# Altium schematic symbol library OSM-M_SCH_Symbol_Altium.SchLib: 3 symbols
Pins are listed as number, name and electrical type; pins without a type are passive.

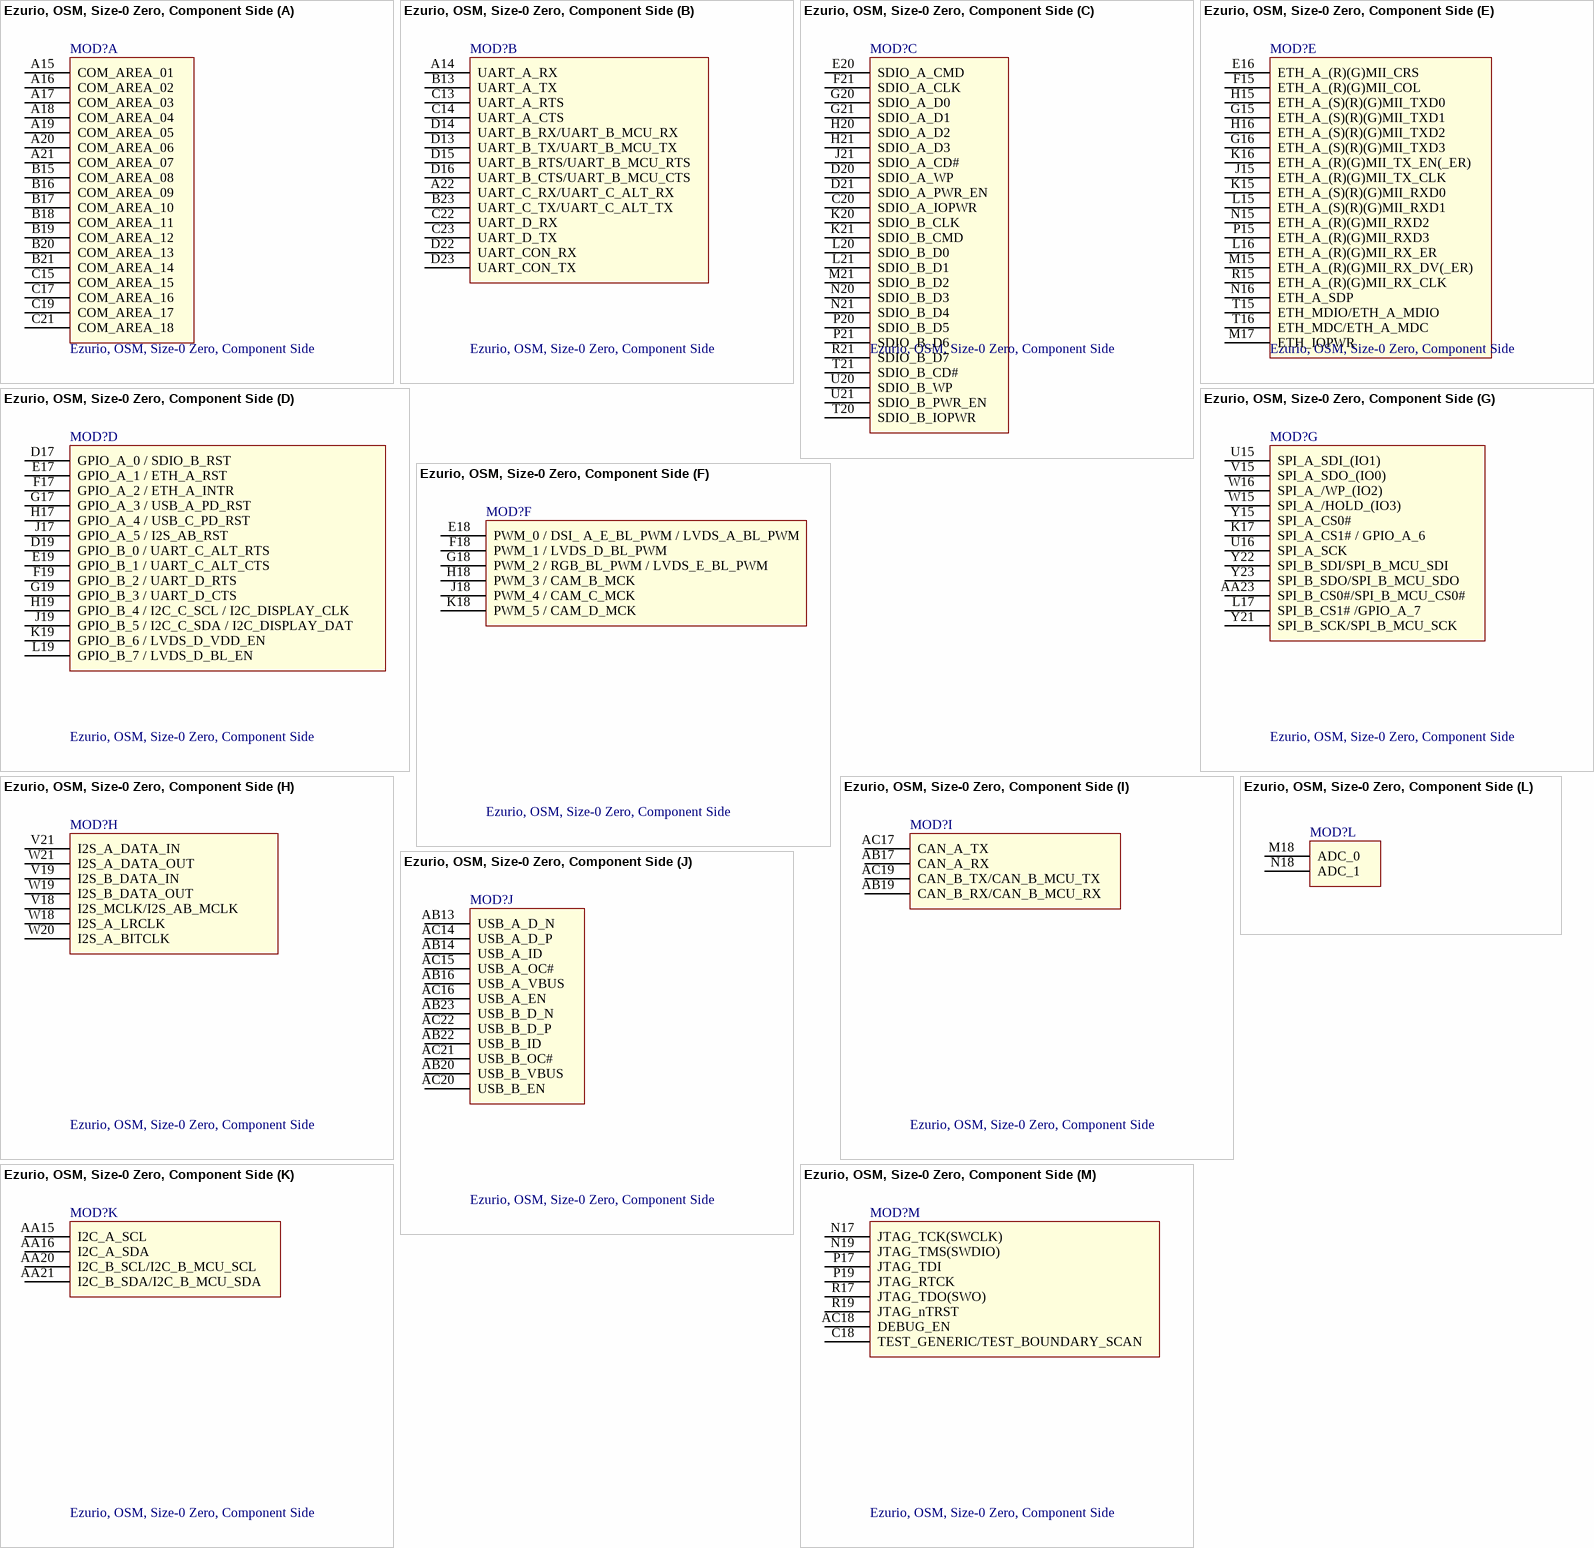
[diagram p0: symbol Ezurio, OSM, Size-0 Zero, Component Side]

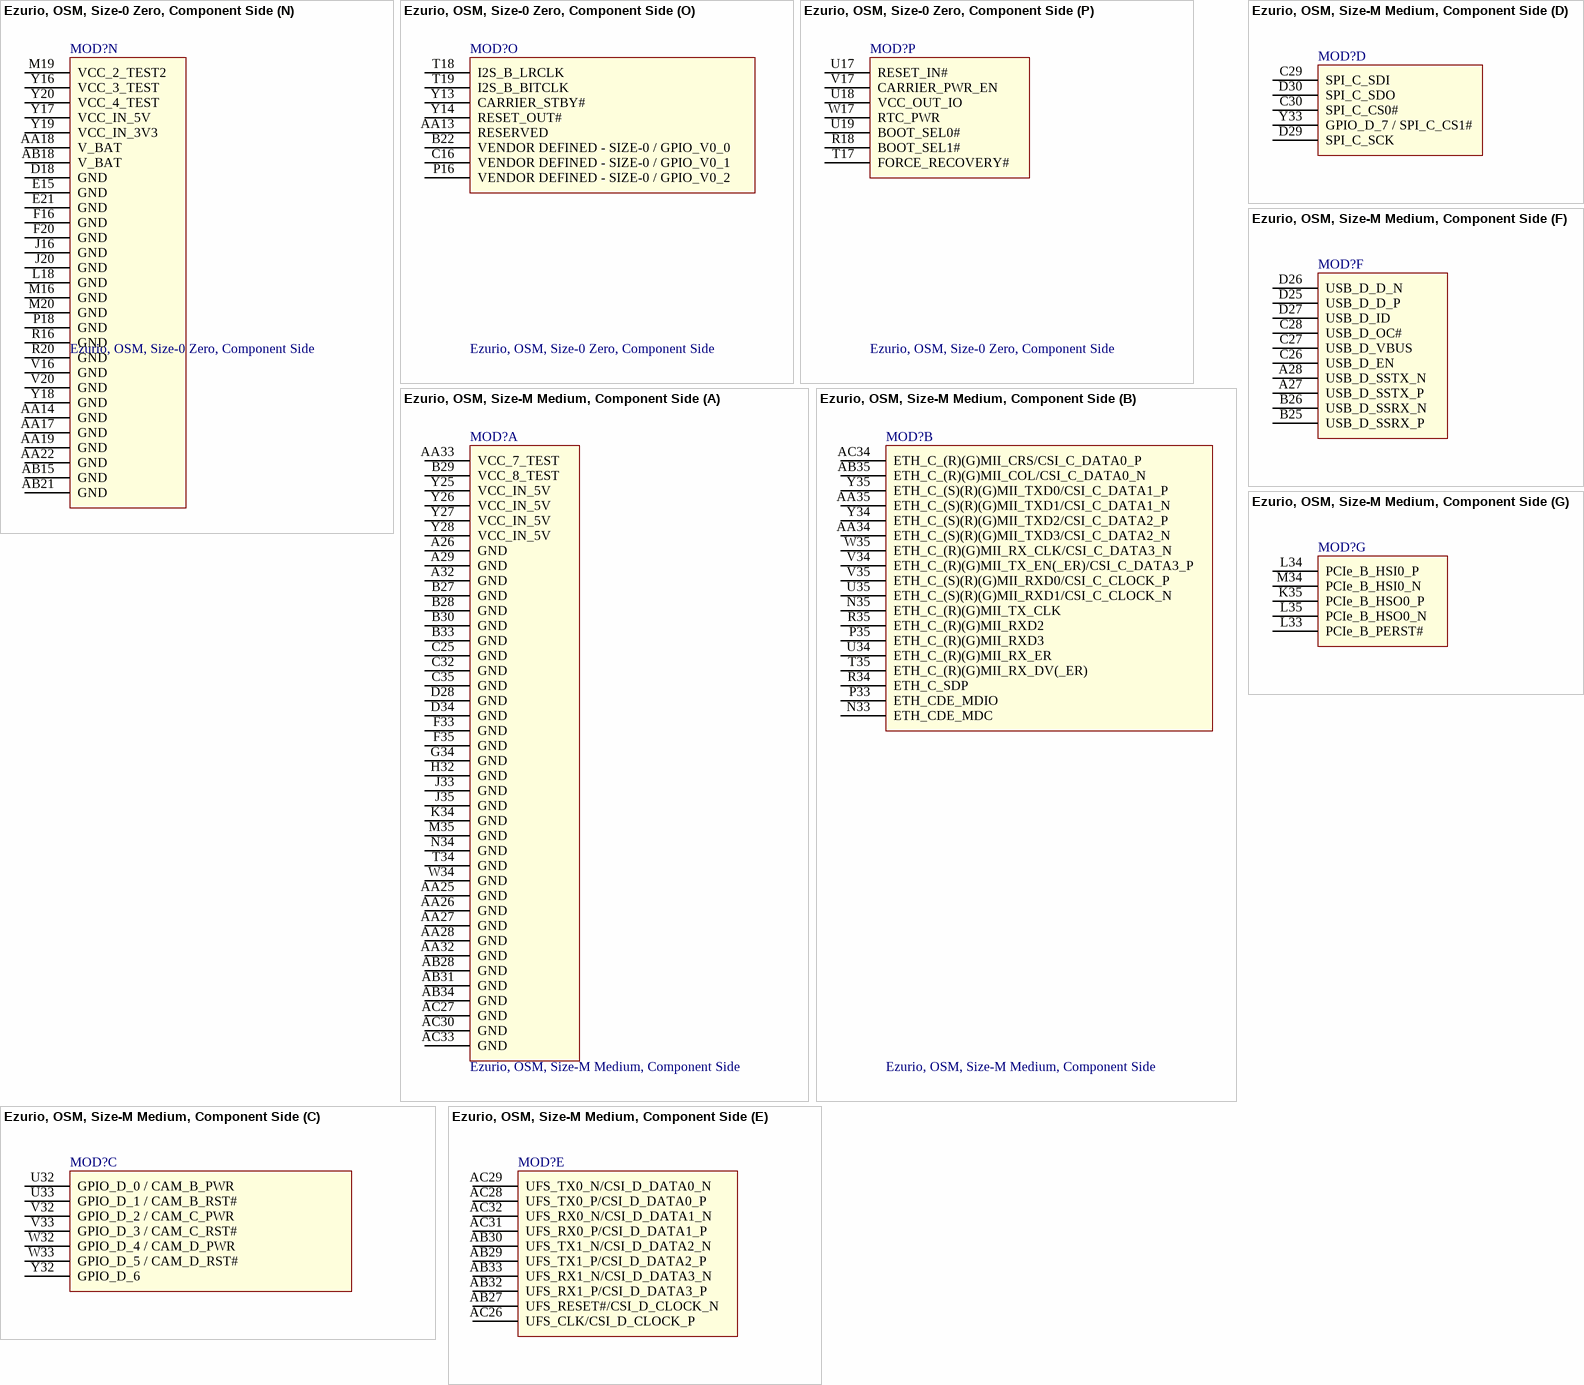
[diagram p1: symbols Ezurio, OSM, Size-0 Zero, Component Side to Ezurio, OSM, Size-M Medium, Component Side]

## Ezurio, OSM, Size-0 Zero, Component Side
designator MOD?
OSM, Size-0 Zero, 30mm X 15mm with 188 contacts; Substitutes Allowed: NO
footprint OSM, Size-0 Zero
part A pins: A15 COM_AREA_01, A16 COM_AREA_02, A17 COM_AREA_03, A18 COM_AREA_04, A19 COM_AREA_05, A20 COM_AREA_06, A21 COM_AREA_07, B15 COM_AREA_08, B16 COM_AREA_09, B17 COM_AREA_10, B18 COM_AREA_11, B19 COM_AREA_12, B20 COM_AREA_13, B21 COM_AREA_14, C15 COM_AREA_15, C17 COM_AREA_16, C19 COM_AREA_17, C21 COM_AREA_18
part B pins: A14 UART_A_RX, A22 UART_C_RX/UART_C_ALT_RX, B13 UART_A_TX, B23 UART_C_TX/UART_C_ALT_TX, C13 UART_A_RTS, C14 UART_A_CTS, C22 UART_D_RX, C23 UART_D_TX, D13 UART_B_TX/UART_B_MCU_TX, D14 UART_B_RX/UART_B_MCU_RX, D15 UART_B_RTS/UART_B_MCU_RTS, D16 UART_B_CTS/UART_B_MCU_CTS, D22 UART_CON_RX, D23 UART_CON_TX
part C pins: C20 SDIO_A_IOPWR, D20 SDIO_A_WP, D21 SDIO_A_PWR_EN, E20 SDIO_A_CMD, F21 SDIO_A_CLK, G20 SDIO_A_D0, G21 SDIO_A_D1, H20 SDIO_A_D2, H21 SDIO_A_D3, J21 SDIO_A_CD#, K20 SDIO_B_CLK, K21 SDIO_B_CMD, L20 SDIO_B_D0, L21 SDIO_B_D1, M21 SDIO_B_D2, N20 SDIO_B_D3, N21 SDIO_B_D4, P20 SDIO_B_D5, P21 SDIO_B_D6, R21 SDIO_B_D7, T20 SDIO_B_IOPWR, T21 SDIO_B_CD#, U20 SDIO_B_WP, U21 SDIO_B_PWR_EN
part D pins: D17 GPIO_A_0 / SDIO_B_RST, D19 GPIO_B_0 / UART_C_ALT_RTS, E17 GPIO_A_1 / ETH_A_RST , E19 GPIO_B_1 / UART_C_ALT_CTS, F17 GPIO_A_2 / ETH_A_INTR, F19 GPIO_B_2 / UART_D_RTS, G17 GPIO_A_3 / USB_A_PD_RST , G19 GPIO_B_3 / UART_D_CTS , H17 GPIO_A_4 / USB_C_PD_RST, H19 GPIO_B_4 / I2C_C_SCL / I2C_DISPLAY_CLK, J17 GPIO_A_5 / I2S_AB_RST, J19 GPIO_B_5 / I2C_C_SDA / I2C_DISPLAY_DAT, K19 GPIO_B_6 / LVDS_D_VDD_EN, L19 GPIO_B_7 / LVDS_D_BL_EN
part E pins: E16 ETH_A_(R)(G)MII_CRS, F15 ETH_A_(R)(G)MII_COL, G15 ETH_A_(S)(R)(G)MII_TXD1, G16 ETH_A_(S)(R)(G)MII_TXD3, H15 ETH_A_(S)(R)(G)MII_TXD0, H16 ETH_A_(S)(R)(G)MII_TXD2, J15 ETH_A_(R)(G)MII_TX_CLK, K15 ETH_A_(S)(R)(G)MII_RXD0, K16 ETH_A_(R)(G)MII_TX_EN(_ER), L15 ETH_A_(S)(R)(G)MII_RXD1, L16 ETH_A_(R)(G)MII_RX_ER, M15 ETH_A_(R)(G)MII_RX_DV(_ER), M17 ETH_IOPWR, N15 ETH_A_(R)(G)MII_RXD2, N16 ETH_A_SDP, P15 ETH_A_(R)(G)MII_RXD3, R15 ETH_A_(R)(G)MII_RX_CLK, T15 ETH_MDIO/ETH_A_MDIO, T16 ETH_MDC/ETH_A_MDC
part F pins: E18 PWM_0 / DSI_ A_E_BL_PWM / LVDS_A_BL_PWM, F18 PWM_1 / LVDS_D_BL_PWM, G18 PWM_2 / RGB_BL_PWM / LVDS_E_BL_PWM, H18 PWM_3 / CAM_B_MCK, J18 PWM_4 / CAM_C_MCK, K18 PWM_5 / CAM_D_MCK
part G pins: AA23 SPI_B_CS0#/SPI_B_MCU_CS0#, K17 SPI_A_CS1# / GPIO_A_6, L17 SPI_B_CS1# /GPIO_A_7, U15 SPI_A_SDI_(IO1), U16 SPI_A_SCK, V15 SPI_A_SDO_(IO0), W15 SPI_A_/HOLD_(IO3), W16 SPI_A_/WP_(IO2), Y15 SPI_A_CS0#, Y21 SPI_B_SCK/SPI_B_MCU_SCK, Y22 SPI_B_SDI/SPI_B_MCU_SDI, Y23 SPI_B_SDO/SPI_B_MCU_SDO
part H pins: V18 I2S_MCLK/I2S_AB_MCLK, V19 I2S_B_DATA_IN, V21 I2S_A_DATA_IN, W18 I2S_A_LRCLK, W19 I2S_B_DATA_OUT, W20 I2S_A_BITCLK, W21 I2S_A_DATA_OUT
part I pins: AB17 CAN_A_RX, AB19 CAN_B_RX/CAN_B_MCU_RX, AC17 CAN_A_TX, AC19 CAN_B_TX/CAN_B_MCU_TX
part J pins: AB13 USB_A_D_N, AB14 USB_A_ID, AB16 USB_A_VBUS, AB20 USB_B_VBUS, AB22 USB_B_ID, AB23 USB_B_D_N, AC14 USB_A_D_P, AC15 USB_A_OC#, AC16 USB_A_EN, AC20 USB_B_EN, AC21 USB_B_OC#, AC22 USB_B_D_P
part K pins: AA15 I2C_A_SCL, AA16 I2C_A_SDA, AA20 I2C_B_SCL/I2C_B_MCU_SCL, AA21 I2C_B_SDA/I2C_B_MCU_SDA
part L pins: M18 ADC_0, N18 ADC_1
part M pins: AC18 DEBUG_EN, C18 TEST_GENERIC/TEST_BOUNDARY_SCAN , N17 JTAG_TCK(SWCLK), N19 JTAG_TMS(SWDIO), P17 JTAG_TDI, P19 JTAG_RTCK, R17 JTAG_TDO(SWO), R19 JTAG_nTRST
part N pins: AA14 GND, AA17 GND, AA18 V_BAT, AA19 GND, AA22 GND, AB15 GND, AB18 V_BAT, AB21 GND, D18 GND, E15 GND, E21 GND, F16 GND, F20 GND, J16 GND, J20 GND, L18 GND, M16 GND, M19 VCC_2_TEST2, M20 GND, P18 GND, R16 GND, R20 GND, V16 GND, V20 GND, Y16 VCC_3_TEST, Y17 VCC_IN_5V, Y18 GND, Y19 VCC_IN_3V3, Y20 VCC_4_TEST
part O pins: AA13 RESERVED, B22 VENDOR DEFINED - SIZE-0 / GPIO_V0_0, C16 VENDOR DEFINED - SIZE-0 / GPIO_V0_1, P16 VENDOR DEFINED - SIZE-0 / GPIO_V0_2, T18 I2S_B_LRCLK, T19 I2S_B_BITCLK, Y13 CARRIER_STBY#, Y14 RESET_OUT#
part P pins: R18 BOOT_SEL1#, T17 FORCE_RECOVERY#, U17 RESET_IN#, U18 VCC_OUT_IO, U19 BOOT_SEL0#, V17 CARRIER_PWR_EN, W17 RTC_PWR

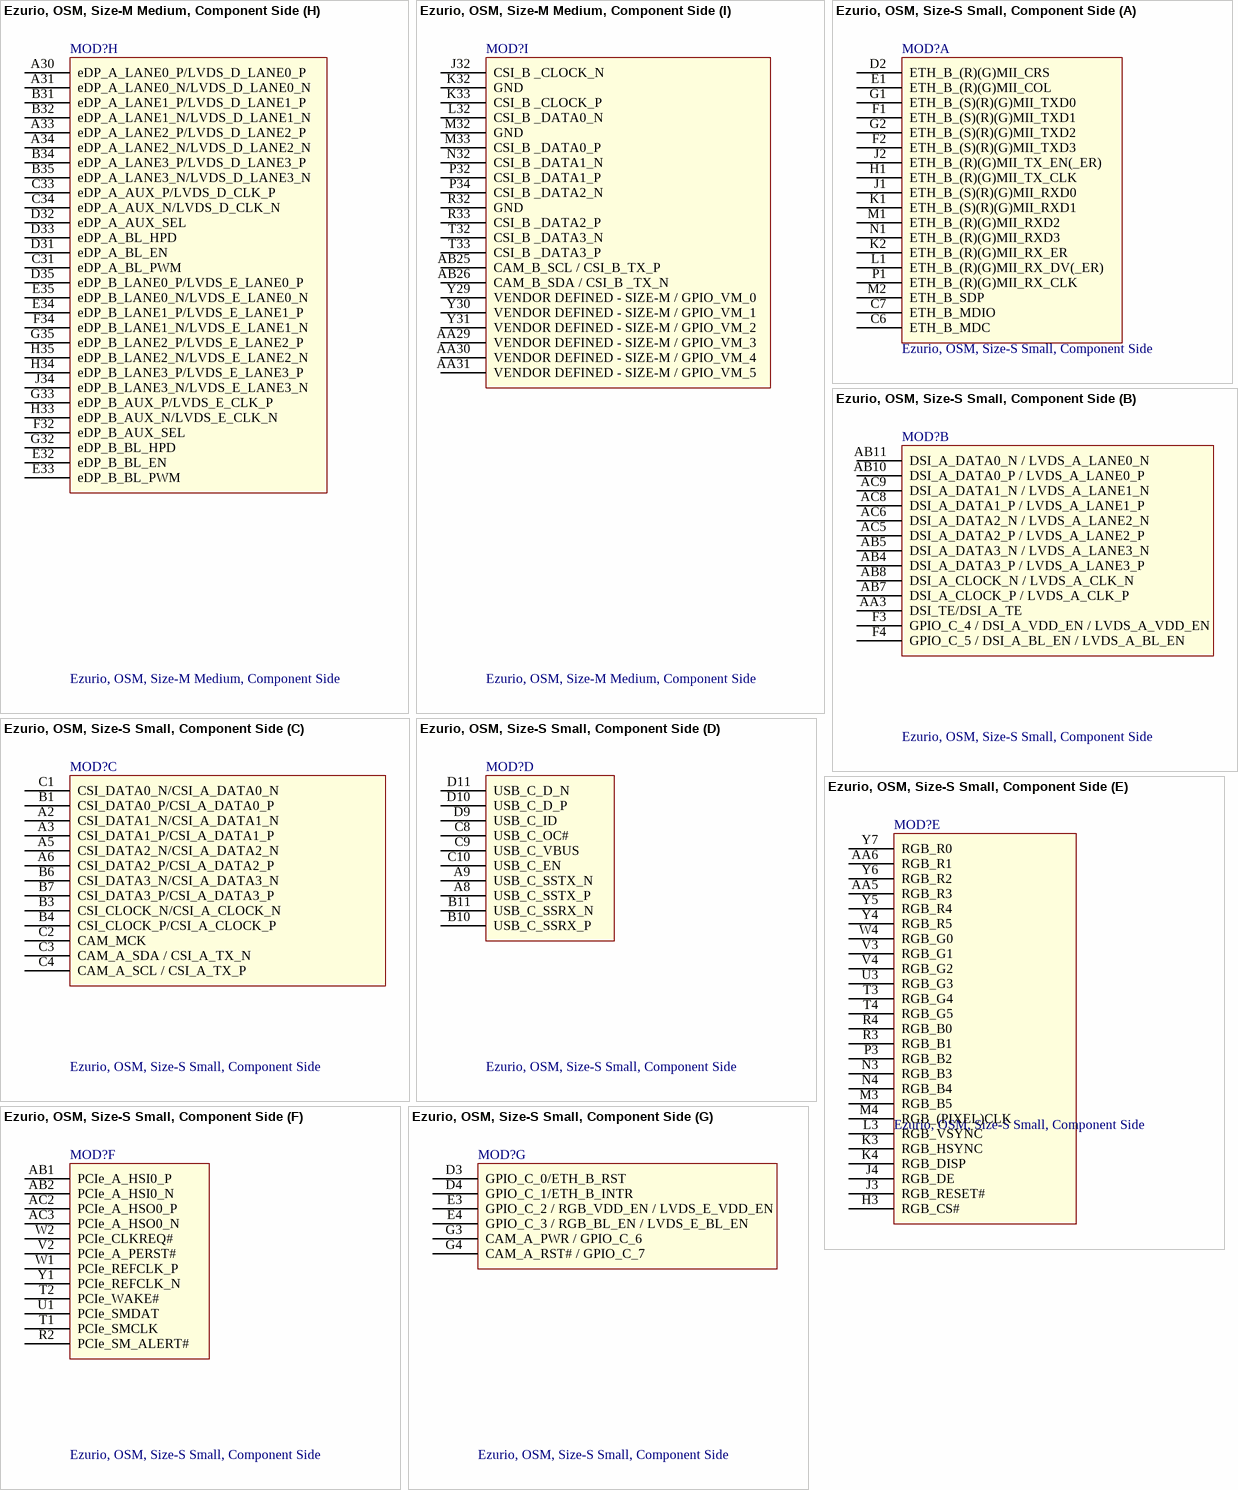
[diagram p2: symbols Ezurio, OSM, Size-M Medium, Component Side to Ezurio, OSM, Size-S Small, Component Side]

## Ezurio, OSM, Size-M Medium, Component Side
designator MOD?
OSM, Size-M Medium, 30mm X 45mm with 476 contacts; Substitutes Allowed: NO
footprint OSM, Size-M Medium
part A pins: A26 GND, A29 GND, A32 GND, AA25 GND, AA26 GND, AA27 GND, AA28 GND, AA32 GND, AA33 VCC_7_TEST, AB28 GND, AB31 GND, AB34 GND, AC27 GND, AC30 GND, AC33 GND, B27 GND, B28 GND, B29 VCC_8_TEST, B30 GND, B33 GND, C25 GND, C32 GND, C35 GND, D28 GND, D34 GND, F33 GND, F35 GND, G34 GND, H32 GND, J33 GND, J35 GND, K34 GND, M35 GND, N34 GND, T34 GND, W34 GND, Y25 VCC_IN_5V, Y26 VCC_IN_5V, Y27 VCC_IN_5V, Y28 VCC_IN_5V
part B pins: AA34 ETH_C_(S)(R)(G)MII_TXD3/CSI_C_DATA2_N, AA35 ETH_C_(S)(R)(G)MII_TXD1/CSI_C_DATA1_N, AB35 ETH_C_(R)(G)MII_COL/CSI_C_DATA0_N, AC34 ETH_C_(R)(G)MII_CRS/CSI_C_DATA0_P, N33 ETH_CDE_MDC, N35 ETH_C_(R)(G)MII_TX_CLK, P33 ETH_CDE_MDIO, P35 ETH_C_(R)(G)MII_RXD3, R34 ETH_C_SDP, R35 ETH_C_(R)(G)MII_RXD2, T35 ETH_C_(R)(G)MII_RX_DV(_ER), U34 ETH_C_(R)(G)MII_RX_ER, U35 ETH_C_(S)(R)(G)MII_RXD1/CSI_C_CLOCK_N, V34 ETH_C_(R)(G)MII_TX_EN(_ER)/CSI_C_DATA3_P, V35 ETH_C_(S)(R)(G)MII_RXD0/CSI_C_CLOCK_P, W35 ETH_C_(R)(G)MII_RX_CLK/CSI_C_DATA3_N, Y34 ETH_C_(S)(R)(G)MII_TXD2/CSI_C_DATA2_P, Y35 ETH_C_(S)(R)(G)MII_TXD0/CSI_C_DATA1_P
part C pins: U32 GPIO_D_0 / CAM_B_PWR, U33 GPIO_D_1 / CAM_B_RST#, V32 GPIO_D_2 / CAM_C_PWR, V33 GPIO_D_3 / CAM_C_RST#, W32 GPIO_D_4 / CAM_D_PWR, W33 GPIO_D_5 / CAM_D_RST#, Y32 GPIO_D_6
part D pins: C29 SPI_C_SDI, C30 SPI_C_CS0#, D29 SPI_C_SCK, D30 SPI_C_SDO, Y33 GPIO_D_7 / SPI_C_CS1#
part E pins: AB27 UFS_RESET#/CSI_D_CLOCK_N, AB29 UFS_TX1_P/CSI_D_DATA2_P, AB30 UFS_TX1_N/CSI_D_DATA2_N, AB32 UFS_RX1_P/CSI_D_DATA3_P, AB33 UFS_RX1_N/CSI_D_DATA3_N, AC26 UFS_CLK/CSI_D_CLOCK_P, AC28 UFS_TX0_P/CSI_D_DATA0_P, AC29 UFS_TX0_N/CSI_D_DATA0_N, AC31 UFS_RX0_P/CSI_D_DATA1_P, AC32 UFS_RX0_N/CSI_D_DATA1_N
part F pins: A27 USB_D_SSTX_P, A28 USB_D_SSTX_N, B25 USB_D_SSRX_P, B26 USB_D_SSRX_N, C26 USB_D_EN, C27 USB_D_VBUS, C28 USB_D_OC#, D25 USB_D_D_P, D26 USB_D_D_N, D27 USB_D_ID
part G pins: K35 PCIe_B_HSO0_P, L33 PCIe_B_PERST#, L34 PCIe_B_HSI0_P, L35 PCIe_B_HSO0_N, M34 PCIe_B_HSI0_N
part H pins: A30 eDP_A_LANE0_P/LVDS_D_LANE0_P, A31 eDP_A_LANE0_N/LVDS_D_LANE0_N, A33 eDP_A_LANE2_P/LVDS_D_LANE2_P, A34 eDP_A_LANE2_N/LVDS_D_LANE2_N, B31 eDP_A_LANE1_P/LVDS_D_LANE1_P, B32 eDP_A_LANE1_N/LVDS_D_LANE1_N, B34 eDP_A_LANE3_P/LVDS_D_LANE3_P, B35 eDP_A_LANE3_N/LVDS_D_LANE3_N, C31 eDP_A_BL_PWM, C33 eDP_A_AUX_P/LVDS_D_CLK_P, C34 eDP_A_AUX_N/LVDS_D_CLK_N, D31 eDP_A_BL_EN, D32 eDP_A_AUX_SEL, D33 eDP_A_BL_HPD, D35 eDP_B_LANE0_P/LVDS_E_LANE0_P, E32 eDP_B_BL_EN, E33 eDP_B_BL_PWM, E34 eDP_B_LANE1_P/LVDS_E_LANE1_P, E35 eDP_B_LANE0_N/LVDS_E_LANE0_N, F32 eDP_B_AUX_SEL, F34 eDP_B_LANE1_N/LVDS_E_LANE1_N, G32 eDP_B_BL_HPD, G33 eDP_B_AUX_P/LVDS_E_CLK_P, G35 eDP_B_LANE2_P/LVDS_E_LANE2_P, H33 eDP_B_AUX_N/LVDS_E_CLK_N, H34 eDP_B_LANE3_P/LVDS_E_LANE3_P, H35 eDP_B_LANE2_N/LVDS_E_LANE2_N, J34 eDP_B_LANE3_N/LVDS_E_LANE3_N
part I pins: AA29 VENDOR DEFINED - SIZE-M / GPIO_VM_3, AA30 VENDOR DEFINED - SIZE-M / GPIO_VM_4, AA31 VENDOR DEFINED - SIZE-M / GPIO_VM_5, AB25 CAM_B_SCL / CSI_B_TX_P, AB26 CAM_B_SDA / CSI_B _TX_N, J32 CSI_B _CLOCK_N, K32 GND, K33 CSI_B _CLOCK_P, L32 CSI_B _DATA0_N, M32 GND, M33 CSI_B _DATA0_P, N32 CSI_B _DATA1_N, P32 CSI_B _DATA1_P, P34 CSI_B _DATA2_N, R32 GND, R33 CSI_B _DATA2_P, T32 CSI_B _DATA3_N, T33 CSI_B _DATA3_P, Y29 VENDOR DEFINED - SIZE-M / GPIO_VM_0, Y30 VENDOR DEFINED - SIZE-M / GPIO_VM_1, Y31 VENDOR DEFINED - SIZE-M / GPIO_VM_2

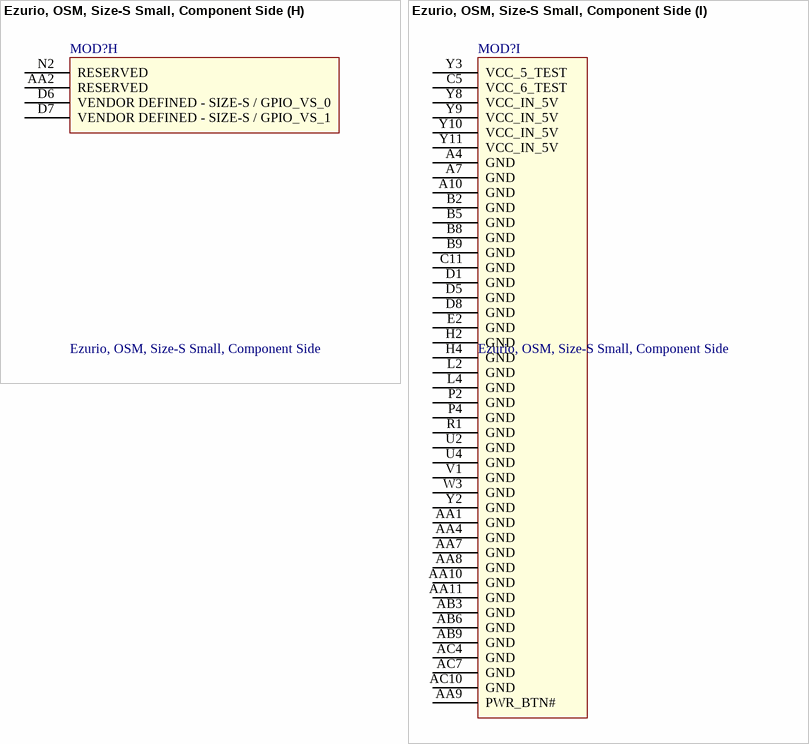
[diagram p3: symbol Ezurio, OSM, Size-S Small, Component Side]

## Ezurio, OSM, Size-S Small, Component Side
designator MOD?
OSM, Size-S Small, 30mm X 30mm with 332 contacts; Substitutes Allowed: NO
footprint OSM, Size-S Small
part A pins: C6 ETH_B_MDC, C7 ETH_B_MDIO, D2 ETH_B_(R)(G)MII_CRS, E1 ETH_B_(R)(G)MII_COL, F1 ETH_B_(S)(R)(G)MII_TXD1, F2 ETH_B_(S)(R)(G)MII_TXD3, G1 ETH_B_(S)(R)(G)MII_TXD0, G2 ETH_B_(S)(R)(G)MII_TXD2, H1 ETH_B_(R)(G)MII_TX_CLK, J1 ETH_B_(S)(R)(G)MII_RXD0, J2 ETH_B_(R)(G)MII_TX_EN(_ER), K1 ETH_B_(S)(R)(G)MII_RXD1, K2 ETH_B_(R)(G)MII_RX_ER, L1 ETH_B_(R)(G)MII_RX_DV(_ER), M1 ETH_B_(R)(G)MII_RXD2, M2 ETH_B_SDP, N1 ETH_B_(R)(G)MII_RXD3, P1 ETH_B_(R)(G)MII_RX_CLK
part B pins: AA3 DSI_TE/DSI_A_TE, AB4 DSI_A_DATA3_P / LVDS_A_LANE3_P, AB5 DSI_A_DATA3_N / LVDS_A_LANE3_N, AB7 DSI_A_CLOCK_P / LVDS_A_CLK_P, AB8 DSI_A_CLOCK_N / LVDS_A_CLK_N, AB10 DSI_A_DATA0_P / LVDS_A_LANE0_P, AB11 DSI_A_DATA0_N / LVDS_A_LANE0_N, AC5 DSI_A_DATA2_P / LVDS_A_LANE2_P, AC6 DSI_A_DATA2_N / LVDS_A_LANE2_N, AC8 DSI_A_DATA1_P / LVDS_A_LANE1_P, AC9 DSI_A_DATA1_N / LVDS_A_LANE1_N, F3 GPIO_C_4 / DSI_A_VDD_EN / LVDS_A_VDD_EN, F4 GPIO_C_5 / DSI_A_BL_EN / LVDS_A_BL_EN
part C pins: A2 CSI_DATA1_N/CSI_A_DATA1_N, A3 CSI_DATA1_P/CSI_A_DATA1_P, A5 CSI_DATA2_N/CSI_A_DATA2_N, A6 CSI_DATA2_P/CSI_A_DATA2_P, B1 CSI_DATA0_P/CSI_A_DATA0_P, B3 CSI_CLOCK_N/CSI_A_CLOCK_N, B4 CSI_CLOCK_P/CSI_A_CLOCK_P, B6 CSI_DATA3_N/CSI_A_DATA3_N, B7 CSI_DATA3_P/CSI_A_DATA3_P, C1 CSI_DATA0_N/CSI_A_DATA0_N, C2 CAM_MCK, C3 CAM_A_SDA / CSI_A_TX_N, C4 CAM_A_SCL / CSI_A_TX_P
part D pins: A8 USB_C_SSTX_P, A9 USB_C_SSTX_N, B10 USB_C_SSRX_P, B11 USB_C_SSRX_N, C8 USB_C_OC#, C9 USB_C_VBUS, C10 USB_C_EN, D9 USB_C_ID, D10 USB_C_D_P, D11 USB_C_D_N
part E pins: AA5 RGB_R3, AA6 RGB_R1, H3 RGB_CS#, J3 RGB_RESET#, J4 RGB_DE, K3 RGB_HSYNC, K4 RGB_DISP, L3 RGB_VSYNC, M3 RGB_B5, M4 RGB_(PIXEL)CLK, N3 RGB_B3, N4 RGB_B4, P3 RGB_B2, R3 RGB_B1, R4 RGB_B0, T3 RGB_G4, T4 RGB_G5, U3 RGB_G3, V3 RGB_G1, V4 RGB_G2, W4 RGB_G0, Y4 RGB_R5, Y5 RGB_R4, Y6 RGB_R2, Y7 RGB_R0
part F pins: AB1 PCIe_A_HSI0_P, AB2 PCIe_A_HSI0_N, AC2 PCIe_A_HSO0_P, AC3 PCIe_A_HSO0_N, R2 PCIe_SM_ALERT#, T1 PCIe_SMCLK, T2 PCIe_WAKE#, U1 PCIe_SMDAT, V2 PCIe_A_PERST#, W1 PCIe_REFCLK_P, W2 PCIe_CLKREQ#, Y1 PCIe_REFCLK_N
part G pins: D3 GPIO_C_0/ETH_B_RST, D4 GPIO_C_1/ETH_B_INTR, E3 GPIO_C_2 / RGB_VDD_EN / LVDS_E_VDD_EN, E4 GPIO_C_3 / RGB_BL_EN / LVDS_E_BL_EN, G3 CAM_A_PWR / GPIO_C_6, G4 CAM_A_RST# / GPIO_C_7
part H pins: AA2 RESERVED, D6 VENDOR DEFINED - SIZE-S / GPIO_VS_0, D7 VENDOR DEFINED - SIZE-S / GPIO_VS_1, N2 RESERVED
part I pins: A4 GND, A7 GND, A10 GND, AA1 GND, AA4 GND, AA7 GND, AA8 GND, AA9 PWR_BTN#, AA10 GND, AA11 GND, AB3 GND, AB6 GND, AB9 GND, AC4 GND, AC7 GND, AC10 GND, B2 GND, B5 GND, B8 GND, B9 GND, C5 VCC_6_TEST, C11 GND, D1 GND, D5 GND, D8 GND, E2 GND, H2 GND, H4 GND, L2 GND, L4 GND, P2 GND, P4 GND, R1 GND, U2 GND, U4 GND, V1 GND, W3 GND, Y2 GND, Y3 VCC_5_TEST, Y8 VCC_IN_5V, Y9 VCC_IN_5V, Y10 VCC_IN_5V, Y11 VCC_IN_5V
